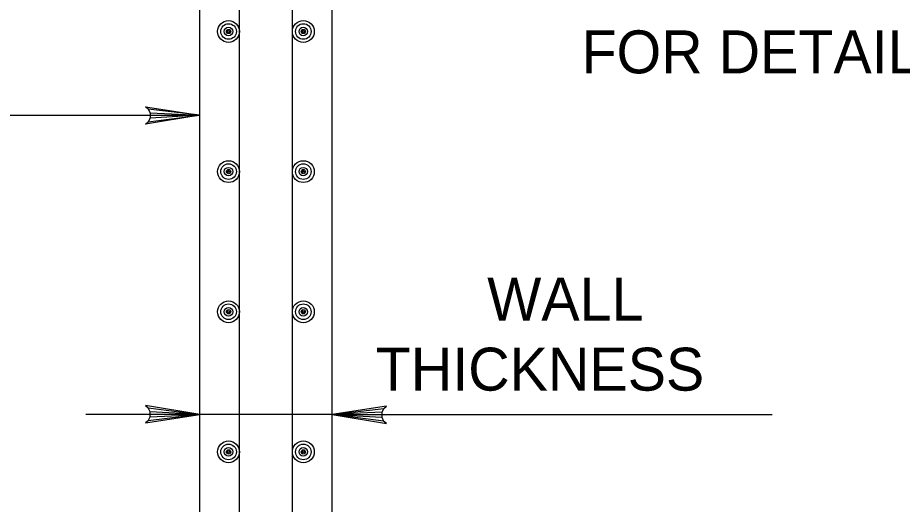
# Model space of a CAD drawing. Extents: x 641328 to 643024, y 298283 to 300065.
# Drawn here: x 641565.3 to 641627.1, y 299664.1 to 299698.1 of the extents above; entities that cross this region are included whole.
import ezdxf

# ---------------------------------------------------------------- set-up
doc = ezdxf.new("R2010")
doc.units = 0
doc.layers.add('2', color=7, linetype='Continuous')

msp = doc.modelspace()

# ---------------------------------------------------------------- linework, layer by layer
at = {"layer": '2'}
for p, q in [((641587.3, 299649.883), (641587.3, 299732.313)), ((641580.826, 299653.408), (641580.826, 299714.305)), ((641584.524, 299653.408), (641584.524, 299714.305)), ((641578.05, 299649.883), (641578.05, 299713.746)), ((641574.441, 299691.722), (641574.248, 299691.882)), ((641574.248, 299691.882), (641578.05, 299691.291)), ((641529.744, 299691.291), (641578.05, 299691.291)), ((641578.05, 299691.291), (641574.256, 299690.657)), ((641574.441, 299691.722), (641574.577, 299691.457)), ((641578.05, 299691.291), (641574.441, 299691.722)), ((641574.452, 299690.833), (641578.05, 299691.291)), ((641574.577, 299691.457), (641578.05, 299691.291)), ((641574.577, 299691.457), (641574.579, 299691.095)), ((641578.05, 299691.291), (641574.578, 299691.276)), ((641578.05, 299691.291), (641574.579, 299691.095)), ((641574.256, 299690.657), (641574.452, 299690.833)), ((641574.579, 299691.095), (641574.452, 299690.833)), ((641578.05, 299670.383), (641574.256, 299671.018)), ((641574.256, 299671.018), (641574.452, 299670.841)), ((641574.579, 299670.579), (641574.452, 299670.841)), ((641574.452, 299670.841), (641578.05, 299670.383)), ((641591.102, 299670.973), (641587.3, 299670.383)), ((641587.3, 299670.383), (641590.91, 299670.814)), ((641590.91, 299670.814), (641590.774, 299670.549)), ((641590.91, 299670.814), (641591.102, 299670.973)), ((641587.3, 299670.383), (641570.097, 299670.383)), ((641574.248, 299669.793), (641578.05, 299670.383)), ((641578.05, 299670.383), (641574.441, 299669.953)), ((641574.441, 299669.953), (641574.577, 299670.217)), ((641574.577, 299670.217), (641574.579, 299670.579)), ((641574.577, 299670.217), (641578.05, 299670.383)), ((641578.05, 299670.383), (641574.578, 299670.398)), ((641578.05, 299670.383), (641574.579, 299670.579)), ((641590.774, 299670.549), (641587.3, 299670.383)), ((641587.3, 299670.383), (641618.048, 299670.383)), ((641587.3, 299670.383), (641590.771, 299670.187)), ((641590.899, 299669.925), (641587.3, 299670.383)), ((641587.3, 299670.383), (641591.095, 299669.749)), ((641587.3, 299670.383), (641590.773, 299670.368)), ((641590.774, 299670.549), (641590.771, 299670.187)), ((641590.771, 299670.187), (641590.899, 299669.925)), ((641574.441, 299669.953), (641574.248, 299669.793)), ((641591.095, 299669.749), (641590.899, 299669.925))]:
    msp.add_line(p, q, dxfattribs=at)
for centre, radius in [((641580.063, 299697.143), 0.763), ((641580.063, 299697.143), 0.545), ((641580.063, 299697.143), 0.298), ((641585.287, 299697.143), 0.763), ((641585.287, 299697.143), 0.545), ((641585.287, 299697.143), 0.298), ((641580.063, 299697.143), 0.15), ((641580.063, 299697.143), 0.0644), ((641585.287, 299697.143), 0.15), ((641585.287, 299697.143), 0.0644), ((641580.063, 299687.353), 0.763), ((641585.287, 299687.353), 0.763), ((641580.063, 299687.353), 0.545), ((641580.063, 299687.353), 0.298), ((641580.063, 299687.353), 0.15), ((641585.287, 299687.353), 0.545), ((641585.287, 299687.353), 0.298), ((641585.287, 299687.353), 0.15), ((641580.063, 299687.353), 0.0644), ((641585.287, 299687.353), 0.0644), ((641580.063, 299677.563), 0.763), ((641585.287, 299677.563), 0.763), ((641580.063, 299677.563), 0.545), ((641580.063, 299677.563), 0.298), ((641580.063, 299677.563), 0.15), ((641580.063, 299677.563), 0.0644), ((641585.287, 299677.563), 0.545), ((641585.287, 299677.563), 0.298), ((641585.287, 299677.563), 0.15), ((641585.287, 299677.563), 0.0644), ((641580.063, 299667.773), 0.763), ((641580.063, 299667.773), 0.545), ((641585.287, 299667.773), 0.763), ((641585.287, 299667.773), 0.545), ((641580.063, 299667.773), 0.298), ((641580.063, 299667.773), 0.15), ((641580.063, 299667.773), 0.0644), ((641585.287, 299667.773), 0.298), ((641585.287, 299667.773), 0.15), ((641585.287, 299667.773), 0.0644)]:
    msp.add_circle(centre, radius, dxfattribs=at)

# ---------------------------------------------------------------- texts
for s, height, p in [('FOR DETAILS', 2.99999, (641604.725, 299694.219)), ('WALL', 3, (641598.134, 299676.951)), ('THICKNESS', 3, (641590.346, 299672.052))]:
    msp.add_text(s, height=height, dxfattribs=at).set_placement(p)

doc.saveas('drawing.dxf')
